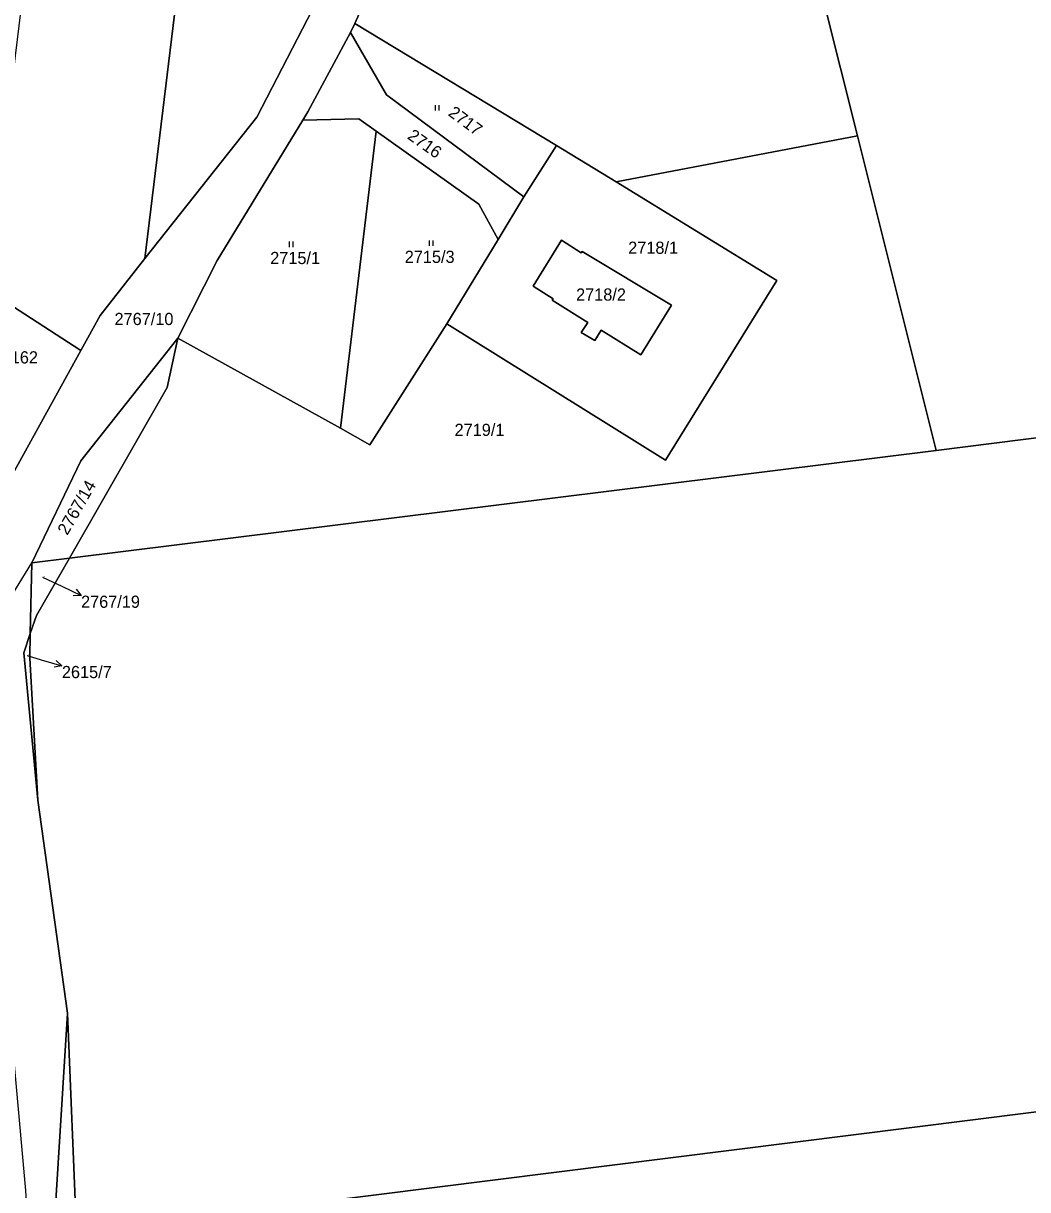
# Model space of a CAD drawing. Extents: x -596024 to -594475, y -1163820 to -1161957.
# Drawn here: x -595521.9 to -595381.8, y -1162891.7 to -1162728.9 of the extents above; entities that cross this region are included whole.
import ezdxf

# ---------------------------------------------------------------- set-up
doc = ezdxf.new("R2010")
doc.units = 0
for name, color, linetype in [('Level 1', 7, 'Continuous'), ('Level 3', 7, 'Continuous'), ('Level 4', 7, 'Continuous'), ('Level 5', 7, 'Continuous'), ('Level 57', 7, 'Continuous'), ('Level 60', 7, 'Continuous')]:
    doc.layers.add(name, color=color, linetype=linetype)

msp = doc.modelspace()

# ---------------------------------------------------------------- linework, layer by layer
at = {"layer": 'Level 1'}
for points in [[(-595504.97, -1162761.74), (-595469.27, -1162467.89)], [(-595450.99, -1162470.45), (-595453.39, -1162511.78), (-595466.35, -1162608.72), (-595477.32, -1162718.69), (-595489.37, -1162742.03), (-595504.97, -1162761.74)], [(-595405.59, -1162744.64), (-595417.38, -1162697.56)], [(-595475.71, -1162728.95), (-595471.35, -1162719.29)], [(-595476.29, -1162730.23), (-595475.71, -1162728.95)], [(-595447.57, -1162745.96), (-595475.71, -1162728.95)], [(-595476.29, -1162730.23), (-595482.23, -1162741.28), (-595482.95, -1162742.46)], [(-595452.1, -1162753.12), (-595471.3, -1162738.92), (-595476.29, -1162730.23)], [(-595500.4, -1162772.85), (-595494.89, -1162762.01), (-595482.95, -1162742.46)], [(-595472.71, -1162743.99), (-595475.16, -1162742.26), (-595482.95, -1162742.46)], [(-595477.71, -1162785.42), (-595472.71, -1162743.99)], [(-595455.72, -1162759.09), (-595458.4, -1162754.16), (-595472.71, -1162743.99)], [(-595405.59, -1162744.64), (-595439.24, -1162751.06)], [(-595394.58, -1162788.54), (-595405.59, -1162744.64)], [(-595452.1, -1162753.12), (-595447.57, -1162745.96)], [(-595439.24, -1162751.06), (-595447.57, -1162745.96)], [(-595462.88, -1162770.88), (-595432.34, -1162789.9), (-595416.84, -1162764.8), (-595439.24, -1162751.06)], [(-595455.72, -1162759.09), (-595452.1, -1162753.12)], [(-595462.88, -1162770.88), (-595455.72, -1162759.09)], [(-595435.79, -1162775.21), (-595431.51, -1162768.24), (-595444, -1162760.77), (-595444.11, -1162760.95), (-595446.86, -1162759.19), (-595450.82, -1162765.62), (-595448.04, -1162767.39), (-595448.15, -1162767.58), (-595443.21, -1162770.67), (-595444.11, -1162772.05), (-595442.21, -1162773.19), (-595441.31, -1162771.75), (-595435.79, -1162775.21)], [(-595513.92, -1162774.56), (-595511.22, -1162769.69), (-595504.97, -1162761.74)], [(-595526.95, -1162766.14), (-595513.92, -1162774.56)], [(-595477.71, -1162785.42), (-595473.62, -1162787.75), (-595462.88, -1162770.88)], [(-595520.75, -1162804.22), (-595513.91, -1162789.97), (-595500.4, -1162772.85)], [(-595500.4, -1162772.85), (-595501.86, -1162779.73), (-595515.52, -1162803.57)], [(-595500.4, -1162772.85), (-595477.71, -1162785.42)], [(-595523.39, -1162791.77), (-595513.92, -1162774.56)], [(-595333.16, -1162780.77), (-595394.58, -1162788.54)], [(-595515.52, -1162803.57), (-595394.58, -1162788.54)], [(-595520.97, -1162814.09), (-595520.11, -1162811.58), (-595515.52, -1162803.57)], [(-595520.97, -1162814.09), (-595520.75, -1162804.22)], [(-595520.75, -1162804.22), (-595515.52, -1162803.57)], [(-595519.91, -1162837.31), (-595521.88, -1162816.77), (-595520.97, -1162814.09)], [(-595519.91, -1162837.31), (-595521.04, -1162817.5), (-595520.97, -1162814.09)], [(-595515.8, -1162867.07), (-595519.91, -1162837.31)], [(-595514.52, -1162897.65), (-595181.57, -1162855.8)], [(-595520.04, -1162919.04), (-595517.73, -1162898.44), (-595515.8, -1162867.07)], [(-595514.52, -1162897.65), (-595515.8, -1162867.07)]]:
    msp.add_lwpolyline(points, dxfattribs=at)
at = {"layer": 'Level 3'}
for points in [[(-595526.67, -1162816.93), (-595524.28, -1162809.99), (-595520.75, -1162804.22)], [(-595526.67, -1162816.93), (-595527.29, -1162829.34), (-595521.65, -1162891.81), (-595520.04, -1162919.04)]]:
    msp.add_lwpolyline(points, dxfattribs=at)
at = {"layer": 'Level 5'}
for p, q in [((-595464.44, -1162741.11), (-595464.44, -1162740.36)), ((-595463.94, -1162741.11), (-595463.94, -1162740.36)), ((-595484.81, -1162760.14), (-595484.81, -1162759.38)), ((-595484.31, -1162760.14), (-595484.31, -1162759.38)), ((-595465.26, -1162759.98), (-595465.26, -1162759.22)), ((-595464.76, -1162759.98), (-595464.76, -1162759.22))]:
    msp.add_line(p, q, dxfattribs=at)
at = {"layer": 'Level 57'}
for p, q in [((-595519.25, -1162806.2), (-595516.59, -1162807.49)), ((-595516.59, -1162807.49), (-595513.89, -1162808.79)), ((-595521.4, -1162817.14), (-595519.43, -1162817.73)), ((-595519.43, -1162817.73), (-595516.56, -1162818.6))]:
    msp.add_line(p, q, dxfattribs=at)
for points in [[(-595514.57, -1162807.91), (-595513.89, -1162808.79), (-595515.01, -1162808.8)], [(-595517.37, -1162817.83), (-595516.56, -1162818.6), (-595517.66, -1162818.79)]]:
    msp.add_lwpolyline(points, dxfattribs=at)
at = {"layer": 'Level 60'}
for points in [[(-595504.83, -1162582.88), (-595501.95, -1162572.37), (-595478.46, -1162491.39), (-595471.74, -1162467.55), (-595469.27, -1162467.89), (-595504.97, -1162761.74), (-595511.22, -1162769.69), (-595513.92, -1162774.56), (-595526.95, -1162766.14), (-595523.01, -1162733.47), (-595519.33, -1162702.99), (-595518.62, -1162697.17), (-595517.46, -1162687.53), (-595516.22, -1162677.27), (-595514.23, -1162660.73), (-595513.54, -1162655.07), (-595512.84, -1162649.25), (-595511.38, -1162637.17), (-595509.85, -1162624.56), (-595508.27, -1162611.41)], [(-595504.97, -1162761.74), (-595469.27, -1162467.89), (-595450.99, -1162470.45), (-595453.39, -1162511.78), (-595466.35, -1162608.72), (-595477.32, -1162718.69), (-595489.37, -1162742.03)], [(-595417.38, -1162697.56), (-595373, -1162637.62), (-595333.16, -1162780.77), (-595394.58, -1162788.54), (-595405.59, -1162744.64)], [(-595417.38, -1162697.56), (-595405.59, -1162744.64), (-595439.24, -1162751.06), (-595447.57, -1162745.96), (-595475.71, -1162728.95), (-595471.35, -1162719.29)], [(-595447.57, -1162745.96), (-595452.1, -1162753.12), (-595471.3, -1162738.92), (-595476.29, -1162730.23), (-595475.71, -1162728.95)], [(-595452.1, -1162753.12), (-595455.72, -1162759.09), (-595458.4, -1162754.16), (-595472.71, -1162743.99), (-595475.16, -1162742.26), (-595482.95, -1162742.46), (-595482.23, -1162741.28), (-595476.29, -1162730.23), (-595471.3, -1162738.92)], [(-595500.4, -1162772.85), (-595494.89, -1162762.01), (-595482.95, -1162742.46), (-595475.16, -1162742.26), (-595472.71, -1162743.99), (-595477.71, -1162785.42)], [(-595473.62, -1162787.75), (-595477.71, -1162785.42), (-595472.71, -1162743.99), (-595458.4, -1162754.16), (-595455.72, -1162759.09), (-595462.88, -1162770.88)], [(-595405.59, -1162744.64), (-595394.58, -1162788.54), (-595515.52, -1162803.57), (-595501.86, -1162779.73), (-595500.4, -1162772.85), (-595477.71, -1162785.42), (-595473.62, -1162787.75), (-595462.88, -1162770.88), (-595432.34, -1162789.9), (-595416.84, -1162764.8), (-595439.24, -1162751.06)], [(-595432.34, -1162789.9), (-595462.88, -1162770.88), (-595455.72, -1162759.09), (-595452.1, -1162753.12), (-595447.57, -1162745.96), (-595439.24, -1162751.06), (-595416.84, -1162764.8)], [(-595435.79, -1162775.21), (-595431.51, -1162768.24), (-595444, -1162760.77), (-595444.11, -1162760.95), (-595446.86, -1162759.19), (-595450.82, -1162765.62), (-595448.04, -1162767.39), (-595448.15, -1162767.58), (-595443.21, -1162770.67), (-595444.11, -1162772.05), (-595442.21, -1162773.19), (-595441.31, -1162771.75)], [(-595431.51, -1162768.24), (-595435.79, -1162775.21), (-595441.31, -1162771.75), (-595442.21, -1162773.19), (-595444.11, -1162772.05), (-595443.21, -1162770.67), (-595448.15, -1162767.58), (-595448.04, -1162767.39), (-595450.82, -1162765.62), (-595446.86, -1162759.19), (-595444.11, -1162760.95), (-595444, -1162760.77)], [(-595523.39, -1162791.77), (-595540.71, -1162766.32), (-595541.75, -1162765.36), (-595526.95, -1162766.14), (-595513.92, -1162774.56)], [(-595208.44, -1162764.97), (-595181.57, -1162855.8), (-595514.52, -1162897.65), (-595515.8, -1162867.07), (-595519.91, -1162837.31), (-595521.04, -1162817.5), (-595520.97, -1162814.09), (-595520.11, -1162811.58), (-595515.52, -1162803.57), (-595394.58, -1162788.54), (-595333.16, -1162780.77), (-595287.09, -1162774.93), (-595245.65, -1162769.68)], [(-595500.4, -1162772.85), (-595501.86, -1162779.73), (-595515.52, -1162803.57), (-595520.75, -1162804.22), (-595513.91, -1162789.97)], [(-595520.97, -1162814.09), (-595520.75, -1162804.22), (-595515.52, -1162803.57), (-595520.11, -1162811.58)], [(-595519.91, -1162837.31), (-595521.88, -1162816.77), (-595520.97, -1162814.09), (-595521.04, -1162817.5)], [(-595181.57, -1162855.8), (-595162.85, -1162919.17), (-595510.44, -1162965.3), (-595511.15, -1162962.97), (-595514.52, -1162897.65)]]:
    msp.add_lwpolyline(points, close=True, dxfattribs=at)
for points in [[(-595517.66, -1162997.16), (-595519.69, -1162990.12), (-595519.93, -1162988.52), (-595515.96, -1162992.22), (-595520.8, -1162972.23), (-595521.48, -1162971.75), (-595522.19, -1162968.12), (-595523.56, -1162952.96), (-595525.6, -1162891.9), (-595529.19, -1162863.89), (-595530.42, -1162854.29), (-595530.89, -1162850.59), (-595533.1, -1162851.55), (-595534.49, -1162834.47), (-595535.08, -1162827.26), (-595534.28, -1162825.28), (-595527.06, -1162806.64), (-595523.39, -1162791.77), (-595513.92, -1162774.56), (-595511.22, -1162769.69), (-595504.97, -1162761.74), (-595489.37, -1162742.03), (-595477.32, -1162718.69)], [(-595471.35, -1162719.29), (-595475.71, -1162728.95), (-595476.29, -1162730.23), (-595482.23, -1162741.28), (-595482.95, -1162742.46), (-595494.89, -1162762.01), (-595500.4, -1162772.85), (-595513.91, -1162789.97), (-595520.75, -1162804.22), (-595520.97, -1162814.09), (-595521.88, -1162816.77), (-595519.91, -1162837.31), (-595515.8, -1162867.07), (-595517.73, -1162898.44)], [(-595419.94, -1163179.11), (-595450.25, -1163091.52), (-595499.58, -1163019.1), (-595508.45, -1162997.67), (-595513.68, -1162981.77), (-595516.17, -1162966.86), (-595520.04, -1162919.04), (-595517.73, -1162898.44), (-595515.8, -1162867.07), (-595514.52, -1162897.65), (-595517.44, -1162932.58), (-595511.15, -1162962.97), (-595510.44, -1162965.3), (-595506.51, -1162978.99), (-595499.13, -1163007.77), (-595489.04, -1163030.12), (-595470.57, -1163058.4), (-595451.73, -1163086.18), (-595449.69, -1163089.73), (-595424.14, -1163156.76), (-595407.54, -1163198.72)]]:
    msp.add_lwpolyline(points, dxfattribs=at)

# ---------------------------------------------------------------- texts
at = {"layer": 'Level 4'}
for s, rotation, p in [('2717', 323.514, (-595462.79, -1162741.7)), ('2716', 324.5989, (-595468.48, -1162744.94)), ('2767/14', 60.1873, (-595515.81, -1162800.46))]:
    msp.add_text(s, height=1.7, rotation=rotation, dxfattribs=at).set_placement(p)
for s, height, p in [('2715/3', 1.7, (-595468.73, -1162762.36)), ('2718/1', 1.7, (-595437.56, -1162761.09)), ('2715/1', 1.7, (-595487.5, -1162762.52)), ('2718/2', 1.7, (-595444.83, -1162767.62)), ('2767/10', 1.7, (-595509.22, -1162771.03)), ('2712/162', 1.7, (-595529.38, -1162776.39)), ('2719/1', 1.7, (-595461.78, -1162786.51)), ('2767/19', 0.1, (-595519.25, -1162806.2)), ('2615/7', 0.1, (-595521.4, -1162817.14))]:
    msp.add_text(s, height=height, dxfattribs=at).set_placement(p)
at = {"layer": 'Level 57'}
for s, p in [('2767/19', (-595513.89, -1162810.49)), ('2615/7', (-595516.56, -1162820.3))]:
    msp.add_text(s, height=1.7, dxfattribs=at).set_placement(p)

doc.saveas('drawing.dxf')
